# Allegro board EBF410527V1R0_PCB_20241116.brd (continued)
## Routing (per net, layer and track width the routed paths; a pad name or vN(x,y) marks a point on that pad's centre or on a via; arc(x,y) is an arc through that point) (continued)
VO_LCDC_D9: length 53.7
  TOP w0.152: J7.22 v1(40.02,51.02) ; v1(27.58,28.96) 27.58,28.95 U3.104
  BOTTOM w0.152: v1(40.02,51.02) 40.5,51.51 40.5,54.36 40.2,54.66 27.43,54.66 26.52,53.74 26.52,50.16 27.76,48.92 27.76,46 29.46,44.3 30.57,44.3 31.11,43.76 31.11,39.97 30.63,39.49 27.91,39.49 27.69,39.27 27.69,29.06 v1(27.58,28.96)
VO_LCDC_D10: length 54.3
  TOP w0.152: v1(39.02,52.02) 39.52,51.52 J7.21 ; U3.38 55.77,19.06 55.5,19.33 55.5,22.2 55.02,22.68 55.02,37.97 55.3,38.25 55.3,38.99 v1(54.73,39.56)
  GND02 w0.152: v1(39.02,52.02) 39.5,51.54 39.5,50.69 40.11,50.09 40.11,45.29 40.41,44.98 44.98,44.98 45.29,44.68 45.29,39.73 45.95,39.07 54.23,39.07 v1(54.73,39.56)
VO_LCDC_D11: length 52.7
  TOP w0.152: v1(54.73,38.56) 54.58,38.42 54.58,22.4 55.07,21.92 55.07,18.26 55.37,17.96 U3.37 ; J7.20 v1(39.02,51.02)
  GND02 w0.152: v1(54.73,38.56) 45.69,38.56 44.83,39.42 44.83,44.27 44.53,44.58 40.11,44.58 39.73,44.96 39.73,49.89 39.02,50.59 v1(39.02,51.02)
VO_LCDC_D12: length 45.2
  TOP w0.152: v1(54.73,41.56) 55.22,41.07 55.22,40.28 54.98,40.04 54.52,40.04 54.24,39.76 54.24,39.75 54.15,39.66 54.15,22.23 54.64,21.74 54.64,17.16 54.94,16.85 U3.36 ; J7.33 45.52,48.46 46.1,47.88 51.03,47.88 52.31,46.6 v1(52.52,46.6)
  BOTTOM w0.152: v1(54.73,41.56) 54.73,41.69 54.31,42.11 54.31,44.45 52.52,46.23 v1(52.52,46.6)
VO_LCDC_D13: length 46.4
  TOP w0.152: U3.35 54.46,15.76 54.15,16.06 54.15,21.54 53.77,21.92 53.77,39.88 54.45,40.56 v1(54.73,40.56) ; v1(51.52,46.6) 50.57,47.55 46,47.55 45.02,48.53 J7.32
  BOTTOM w0.152: v1(54.73,40.56) 54.24,41.04 54.24,41.74 54,41.99 54,44.3 51.7,46.6 v1(51.52,46.6)
VO_LCDC_D14: length 47.1
  TOP w0.152: v1(50.52,46.6) 50.43,46.6 49.89,47.14 45.98,47.14 44.52,48.6 J7.31 ; v1(53.73,40.56) 53.73,40.39 53.31,39.98 53.31,21.72 53.72,21.31 53.72,15.24 54.31,14.66 U3.34
  BOTTOM w0.152: v1(50.52,46.6) 50.52,46.12 50.93,45.72 51.56,45.72 53.24,44.04 53.24,41.04 v1(53.73,40.56)
VO_LCDC_D15: length 49.5
  TOP w0.152: J7.30 44.02,48.67 45.92,46.76 49.36,46.76 v1(49.52,46.6) ; U3.33 54.59,13.55 53.34,14.81 53.34,21.01 52.91,21.44 52.91,40.06 53.21,40.36 53.21,40.38 53.21,40.39 53.21,41.05 v1(53.73,41.56)
  BOTTOM w0.152: v1(53.73,41.56) 53.67,41.62 53.67,44.15 51.71,46.1 51.26,46.1 51.04,46.32 51.04,46.81 50.76,47.09 50.02,47.09 v1(49.52,46.6)
VO_LCDC_D16: length 52.2
  TOP w0.152: J7.29 v1(43.52,48.74) ; U3.31 55.27,11.36 52.48,14.15 52.48,20.45 52.12,20.8 52.12,40.96 v1(52.73,41.56)
  GND02 w0.152: v1(52.73,41.56) 48.66,41.56 47.85,42.37 47.85,47.42 47.55,47.73 43.82,47.73 43.52,48.03 v1(43.52,48.74)
VO_LCDC_D17: length 51.9
  TOP w0.152: J7.28 43.02,49.09 42.67,48.74 v1(42.52,48.74) ; v1(52.73,40.56) 52.53,40.36 52.53,21.08 52.91,20.7 52.91,14.48 54.93,12.45 U3.32
  GND02 w0.152: v1(42.52,48.74) 42.52,47.5 42.82,47.19 47.09,47.19 47.4,46.89 47.4,42.04 48.87,40.56 v1(52.73,40.56)
VO_LCDC_DEN: length 46.9
  TOP w0.152: v1(32.41,47.85) 33.02,48.47 J7.8 ; v1(37.97,38.59) 40.25,38.59 41.15,37.69 41.15,30.91 40.69,30.45 40.69,23.24 42.01,21.92 42.01,11.94 40.73,10.65 U3.15
  BOTTOM w0.152: v1(32.41,47.85) 32.51,47.85 34.7,45.67 34.7,42.11 37.97,38.84 v1(37.97,38.59)
VO_LCDC_HSYNC: length 42.7
  TOP w0.152: v1(37.97,37.59) 38.46,38.07 40.08,38.07 40.77,37.39 40.77,31.06 40.36,30.66 40.36,22.91 41.53,21.74 41.53,12.57 39.63,10.67 U3.14
  BOTTOM w0.152: R96.1 34.32,45.26 34.32,41.96 37.37,38.91 37.37,38.4 37.97,37.8 v1(37.97,37.59)
VO_LCDC_VSYNC: length 40.7
  TOP w0.152: v1(39.24,37.59) 39.93,37.59 40.41,37.11 40.41,31.24 40.01,30.84 40.01,12.12 38.52,10.64 U3.13
  BOTTOM w0.152: v1(39.24,37.59) 39.24,38.03 35.03,42.24 35.03,46.18 R97.1
WIFI_PWR_EN: length 33.6
  TOP w0.152: R52.1 68.15,33.61 68.15,23.4 v1(68.01,23.27)
  BOTTOM w0.152: v1(68.01,23.27) 67.53,23.75 66.8,23.75 66.53,23.47 66.53,21.97 66.22,21.66 50.25,21.66 49.76,22.14 U5.6
XL9535_INT: length 48.4
  TOP w0.152: U3.114 29.75,17.96 31.64,16.06 v1(31.64,12.12) ; v1(48.95,13.94) 48.95,21.74 50.06,22.86 50.06,23.67 48.77,24.97 v1(48.77,29.08)
  BOTTOM w0.152: R25.1 48.52,29.08 v1(48.77,29.08) ; v1(31.64,12.12) 31.92,12.4 42.55,12.4 44.09,13.94 v1(48.95,13.94)
N19537137: length 11.4
  TOP w0.203: U17.8 62.99,45.47 62.74,45.21 60.07,45.21 59.69,45.59 59.69,48.9 58.93,49.66 57.66,49.66 57.35,49.97 J11.1
N19537140: length 26.3
  TOP w0.203: 66.45,44.02 59.49,44.02 58.8,44.7 58.8,48.36 58.39,48.77 56.35,48.77 56.1,49.02 J11.2 ; 66.45,44.02 66.8,44.37 U17.5 ; 66.45,44.02 66.9,43.56 66.9,43.08 67.64,42.34 67.64,39.17 68.07,38.73 68.7,38.73 R86.2
N19537426: length 4.3
  TOP w0.203: U17.4 66.8,38.6 R85.2
  TOP w0.254: R86.1 R85.2
N19538834: length 6.4
  TOP w0.203: v1(65.53,39.85) U17.3 65.53,42.27 65.3,42.49 64.57,42.49 64.26,42.19 U17.2
  BOTTOM w0.254: C55.1 67.04,39.85 v1(65.53,39.85)
N21425973: length 2.3
  TOP w0.152: J1.A5 79.56,11.04 v1(79.81,10.79)
  BOTTOM w0.152: R5.1 v1(79.81,10.79)
N21425975: length 2.3
  TOP w0.152: J1.B5 v1(79.76,14.04)
  BOTTOM w0.152: R4.1 79.96,13.84 v1(79.76,14.04)
N21432968: length 9.3
  TOP w0.157: v1(83.24,12.77) 82.93,12.47 82.02,12.47 81.52,11.97 79.66,11.97 79.59,12.04 ; 79.59,12.04 79.68,12.13 79.68,12.9 79.54,13.04 J1.B6 ; 79.59,12.04 J1.A6
  BOTTOM w0.157: R2.1 82.54,12.83 D1.2 83.18,12.84 v1(83.24,12.77)
N21432971: length 10.3
  TOP w0.157: J1.A7 77.25,12.54 77.09,12.38 77.09,11.7 77.25,11.54 J1.B7 79.59,11.54 79.66,11.61 81.67,11.61 82.17,12.11 82.93,12.11 v1(83.24,11.81)
  BOTTOM w0.157: v1(83.24,11.81) 82.56,11.81 D2.2 82.54,11.81 R3.1
N23042290: length 3.8
  TOP w0.152: v1(32.41,3.17) 32.41,1.96 32.78,1.58 LED2.2
  BOTTOM w0.152: R9.2 32.51,3.28 v1(32.41,3.17)
N23042305: length 3.4
  TOP w0.152: Q1.3 36.49,3.49 35.61,2.62 LED2.1
N23503644: length 8.9
  TOP w0.152: 15.77,42.17 15.6,42.34 15.6,43.31 15.42,43.48 15.14,43.48 14.94,43.28 14.94,42.56 14.78,42.41 14.57,42.41 14.33,42.65 14.33,43.08 14.17,43.23 13.67,43.23 13.36,43.54 13.36,43.97 13.59,44.19 J2.1
  TOP w0.157: 15.77,42.17 D10.1 R16.2
N23503648: length 6.8
  TOP w0.152: D9.1 16.1,44.2 15.8,44.5 15.8,45.04 15.54,45.29
  TOP w0.157: D9.1 16.9,44.64 17.17,44.91 19.13,44.91 19.44,44.59 R17.2 ; 15.54,45.29 J2.2
N23503652: length 7.6
  TOP w0.157: J2.3 15.46,46.39 15.62,46.55 15.62,46.79 15.77,46.94 16.05,46.94 16.33,46.66 16.33,45.64 16.51,45.47 D8.1 16.9,45.88 17.17,46.15 19.18,46.15 19.44,45.89 R18.2
N23503668: length 7.9
  TOP w0.157: J2.7 15.37,50.79 15.57,50.59 15.57,48.7 15.73,48.54 16.36,48.54 D6.1 17.51,48.62 19.23,48.62 19.44,48.4 R19.2
N23503672: length 19
  TOP w0.157: R20.2 18.84,41.1 17.48,41.1 D5.1 16.31,41.1 14.3,41.1 12.29,43.1 12.29,50.75 13.44,51.89 J2.8
N23503676: length 10.5
  TOP w0.157: R21.2 19.44,49.57 19.08,49.94 17.69,49.94 D4.1 16.75,49 16.21,49 16,49.2 16,49.73 16.16,49.89 16.48,49.89 16.61,50.01 16.61,50.39 16.48,50.52 16.15,50.52 15.95,50.72 15.95,52.68 15.64,52.99 J2.9
N23656759: length 5.5
  TOP w0.254: U2.5 v1(71.31,9.04)
  BOTTOM w0.254: R10.2 C5.2 R13.1 70.7,9.65 v1(71.31,9.04)
N23695731: length 5.9
  BOTTOM w0.157: Y1.3 38.6,16.55 38.38,16.76 38.38,19.07 C15.1 38.5,19.72 U6.3
N23695751: length 4.4
  BOTTOM w0.157: U6.4 38,19.72 C16.2 38.07,19.12 38.07,18.21 37.91,18.05 Y1.1
N23695813: length 2.2
  BOTTOM w0.152: R43.2 39.5,26.3 U6.18
N23695825: length 1.8
  BOTTOM w0.152: U6.16 38.5,27.29 R41.2
N23695839: length 2
  BOTTOM w0.152: U6.17 39,26.82 R39.2
N23695875: length 2
  BOTTOM w0.152: U6.13 37,26.89 R44.1
N23697039: length 1.7
  BOTTOM w0.152: R48.1 1.82,23.84 U8.3
N23697128: length 4
  BOTTOM w0.152: R46.1 2.35,32.92 2.35,30.92 1.82,30.39 U7.3
N23704623: length 11.7
  BOTTOM w0.152: U15.4 68.49,49.49 68.71,49.28 69.97,49.28 R67.2 R68.1 71.47,48.79 72.73,48.79 73.03,49.09 73.03,50.93 73.41,51.31 75.82,51.31 76.11,51.02 U16.4
N23704651: length 4
  BOTTOM w0.152: U16.3 76.11,53.65 76.3,53.85 77.24,53.85 77.44,53.64 R69.1
N23704740: length 4.1
  BOTTOM w0.152: U15.3 68.49,53.63 68.68,53.82 69.8,53.82 69.98,53.64 R66.1
N23717309: length 26.6
  TOP w1.016: R77.1 19.05,20.45 C47.1 17.02,18.36 16.18,17.53 J8.13
  BOTTOM w1.016: J8.13 J8.14
N23717611: length 6
  TOP w0.152: C46.1 18.09,14.23 17.68,13.82 17.68,11.68 16.41,10.42 J8.4
N23717616: length 7.5
  TOP w0.152: J8.5 13.85,8.5 15.82,6.53 18.86,6.53 C45.1
N23717674: length 11.2
  BOTTOM w0.124: R73.2 20.89,8.79 20.55,9.13 18.83,9.13 18.24,9.72 18.24,11.34 18.05,11.53 15.77,11.53 14.94,12.37 14.94,13.15 J8.1
N23717677: length 11.8
  BOTTOM w0.124: J8.2 16.39,13.72 16.15,13.97 15.51,13.97 15.26,13.72 15.26,12.51 15.91,11.86 18.19,11.86 18.57,11.48 18.57,9.86 18.96,9.46 20.55,9.46 20.89,9.8 R72.2
N23717680: length 11.1
  BOTTOM w0.124: R71.2 20.89,7.77 20.55,7.43 18.46,7.43 18.18,7.71 18.18,8.84 17.74,9.28 15.38,9.28 15.04,9.63 15.04,11.4 14.75,11.69 J8.3
N23717683: length 9.4
  BOTTOM w0.124: J8.6 15.56,7.88 15.34,8.1 15.34,8.71 15.59,8.95 17.6,8.95 17.85,8.71 17.85,7.57 18.32,7.1 20.55,7.1 20.89,6.76 R70.2
N23718997: length 3.7
  TOP w0.508: U10.2 C26.1 C24.2
N23719030: length 3.8
  TOP w0.152: Q2.1 68.27,34.86 R52.2 68.33,35.81 R51.2 C27.2
N23719056: length 5.9
  TOP w0.157: U10.4 63.62,27.2 63.78,27.36 65.38,27.36 v1(65.68,27.06)
  BOTTOM w0.157: v1(65.68,27.06) 66.01,27.38 66.91,27.38 67.24,27.05 R50.2
N23719058: length 5.9
  TOP w0.157: U10.5 63.62,27.87 63.78,27.72 65.38,27.72 v1(65.68,28.02)
  BOTTOM w0.157: R49.2 67.24,28.07 66.91,27.74 65.96,27.74 v1(65.68,28.02)
N23719088: length 3.1
  TOP w0.508: CN1.1 C25.1 C24.1
N23722440: length 10.9
  TOP w0.203: R81.2 76.97,47.9 76.52,47.9 75.84,47.22 74.24,47.22 73.58,47.88 72.13,47.88 C48.1 70.86,47.88 70.03,47.88 69.47,47.32 R79.2
N23723488: length 3.5
  TOP w0.203: R80.2 68.46,46.1 C49.1 R82.2
N23729410: length 2.1
  TOP w0.152: v1(28.07,5.53) 28.06,5.52 Q3.1
  BOTTOM w0.152: R76.2 27.48,4.94 v1(28.07,5.53)
N23729602: length 2.1
  TOP w0.152: v1(31.7,5.28) 31.46,5.28 31.22,5.52 Q4.1
  BOTTOM w0.152: R78.2 31.36,4.94 v1(31.7,5.28)
N23729707: length 21.3
  TOP w0.152: R75.2 18.25,17.26 16.92,15.93 12.24,15.93 9.25,12.93 4.19,12.93 3.89,13.23 3.89,15.12 J8.9
N23729710: length 40.8
  TOP w0.152: Q4.3 30.33,4.57 30.02,4.88 30.02,5.84 29.65,6.21 26.5,6.21 26.16,6.55 20.88,6.55 20.27,5.94 20.27,4.62 19.89,4.24 14.25,4.24 10.85,7.65 2.91,7.65 2.61,7.95 J8.10
N23729715: length 31.4
  TOP w0.152: Q3.3 26.7,4.57 26.34,4.93 26.34,5.84 25.97,6.21 21.03,6.21 20.65,5.83 20.65,4.47 20.02,3.84 13.63,3.84 10.41,7.06 3.97,7.06 J8.11
N23729724: length 21.5
  TOP w0.152: R74.2 14.39,2.29 10.16,6.53 5.16,6.53 4.65,6.02 4.65,3.58 4.22,3.15 J8.12
N23759751: length 2.3
  TOP w0.152: v1(35.36,5.13) 35.36,5.22 35.05,5.52 Q1.1
  BOTTOM w0.152: R11.2 35.17,4.94 v1(35.36,5.13)
N23760169: length 2.6
  TOP w0.152: LED1.2 28.52,2.61 v1(29.08,3.17)
  BOTTOM w0.152: v1(29.08,3.17) R8.2
N23768401: length 2.6
  BOTTOM w0.152: R93.1 R59.2 68.51,44.27 U13.4
N23768412: length 2.9
  BOTTOM w0.152: R60.1 69.33,45.86 68.51,46.68 U13.3
N23768535: length 2.5
  BOTTOM w0.152: U14.4 47,45.23 R92.1 R61.2
N23768546: length 1.4
  BOTTOM w0.152: U14.3 47.27,47.73 R62.1
N23809669: length 23.8
  TOP w0.152: R53.2 19.43,34.37 19.96,34.89 19.96,35.79 R56.2 20.02,36.9 20.02,37.9 19.44,38.47 C30.1 18.91,37.95 17.63,37.95 17.42,37.74 17.42,36.47 17.27,36.32 U12.5 16.21,36.32 14.76,37.77 11.96,37.77 11.4,38.33 v1(11.4,42.76)
  BOTTOM w0.152: J14.7 v1(11.4,42.76)
N23809673: length 20.1
  TOP w0.152: R55.2 C32.1 16.85,34.19 U12.6 16.22,35.82 14.66,37.39 11.63,37.39 10.79,38.24 v1(10.79,44.03)
  BOTTOM w0.152: J14.2 v1(10.79,44.03)
N23809721: length 14.8
  TOP w0.157: v1(16.11,38.22) 16.11,37.32 16.6,36.82 U12.4 16.85,38.45 C31.1 R54.2
  BOTTOM w0.157: J14.3 12.11,41.49 11.89,41.27 11.89,38.61 12.27,38.23 16.1,38.23 v1(16.11,38.22)
N23809831: length 2.6
  BOTTOM w0.157: R58.1 31.81,32.79 31.13,32.79 30.91,33.01 J4.38
N23809847: length 2.6
  BOTTOM w0.157: R57.1 31.81,32.43 31.13,32.43 30.91,32.21 J4.36
N23819356: length 6.9
  TOP w0.152: R87.2 D11.2 80.54,30.52 ; 80.54,30.52 80.84,30.22 SW2.3 ; 80.54,30.52 80.84,30.83 SW2.4
N23820735: length 1
  TOP w0.254: R85.1 C54.2
N23825175: length 3
  BOTTOM w0.152: U5.24 47.96,26.04 48.62,26.7 49.17,26.7 R28.2
N23825177: length 2.8
  BOTTOM w0.152: R27.2 48.12,26.67 47.68,26.67 47.46,26.45 U5.23
N23825179: length 3.2
  BOTTOM w0.152: U5.18 44.76,25.99 R26.2
N23825209: length 2.4
  BOTTOM w0.152: U5.19 45.46,26.3 R23.2
N23825224: length 2.2
  BOTTOM w0.152: U5.20 45.96,26.82 R24.2
N23825226: length 2.3
  BOTTOM w0.152: U5.22 46.96,26.52 R25.2
N23825314: length 6.7
  BOTTOM w0.152: U4.6 46.31,29.94 46.66,29.59 50.5,29.59 50.8,29.29 R22.2
N23848065: length 6.9
  TOP w0.152: 80.59,37.89 80.84,38.14 SW3.4 ; 80.59,37.89 D12.2 R90.2 ; 80.59,37.89 80.84,37.63 SW3.3
N23848217: length 9.3
  TOP w0.152: SW4.3 80.84,45.03 80.61,45.25 ; 80.61,45.25 D13.2 R91.2 80.14,47 80.14,48.01 79.63,48.51 R94.1 ; 80.61,45.25 80.84,45.48 SW4.4
N23865153: length 2.8
  TOP w0.152: v1(33.41,47.85) 33.52,47.97 J7.9
  BOTTOM w0.152: v1(33.41,47.85) 33.91,47.35 R97.2
N23865156: length 7.2
  TOP w0.152: v1(31.41,47.85) 31.89,47.37 33.66,47.37 34.02,47.74 J7.10
  BOTTOM w0.152: R96.2 32.21,47.37 32.21,47.37 31.72,47.85 v1(31.41,47.85)
N23865159: length 8.4
  TOP w0.157: J7.11 34.52,47.45 33.93,46.86 31.98,46.86 v1(31.95,46.89)
  BOTTOM w0.157: R95.2 33.78,44.98 31.95,46.81 v1(31.95,46.89)

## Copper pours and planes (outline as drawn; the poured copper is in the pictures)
GND on TOP: 3,0.51 1.24,1.24 0.51,3 0.51,53 1.24,54.76 3,55.49 16,55.49 16.35,55.35 16.49,55 16.49,52.5 18.5,50.49 20.51,52.5 20.51,55 20.65,55.35 21,55.49 82,55.49 83.76,54.76 84.49,53 84.49,3 83.76,1.24 82,0.51 ; 216 cut-outs
GND on BOTTOM: 3,0.51 1.24,1.24 0.51,3 0.51,53 1.24,54.76 3,55.49 16,55.49 16.35,55.35 16.49,55 16.49,52.5 18.5,50.49 20.51,52.5 20.51,55 20.65,55.35 21,55.49 82,55.49 83.76,54.76 84.49,53 84.49,3 83.76,1.24 82,0.51 ; 144 cut-outs
GND on GND02: 3,0.51 1.24,1.24 0.51,3 0.51,53 1.24,54.76 3,55.49 16,55.49 16.35,55.35 16.49,55 16.49,52.5 18.5,50.49 20.51,52.5 20.51,55 20.65,55.35 21,55.49 82,55.49 83.76,54.76 84.49,53 84.49,3 83.76,1.24 82,0.51 ; 38 cut-outs
GND on PWR03: 3,0.51 1.24,1.24 0.51,3 0.51,53 1.24,54.76 3,55.49 16,55.49 16.35,55.35 16.49,55 16.49,52.5 18.5,50.49 20.51,52.5 20.51,55 20.65,55.35 21,55.49 82,55.49 83.76,54.76 84.49,53 84.49,3 83.76,1.24 82,0.51
VCC5V0_SYS on TOP: 68.55,41.58 69.19,41.58 69.39,41.78 69.39,42.14 69.57,42.32 70.51,42.32 70.92,41.91 70.92,40.44 70.64,40.16 69.65,40.16 69.01,40.79 68.55,40.79
VCC5V0_SYS on TOP: 79.35,10.19 76.4,10.19 76.28,10.31 76.28,12.97 77,13.69 77,14.19 77.22,14.4 79.35,14.4 79.35,15.01 75.54,15.01 74.75,14.22 74.75,9.37 74.47,9.09 72.19,9.09 71.96,8.86 71.96,7.47 71.78,7.29 70.51,7.29 70.36,7.44 70.36,8.41 69.98,8.79 69.04,8.79 68.96,8.71 68.96,6.02 69.27,5.71 75.9,5.71 76.2,6.02 76.2,7.21 77.11,8.13 77.11,9.47 77.24,9.6 79.35,9.6
VCC5V0_SYS on TOP: 51.44,46.15 51.44,42.67 51.64,42.47 52.83,42.47 53.14,42.77 53.14,46.15
VCC5V0_SYS on BOTTOM: 3.4,27.99 3.63,28.22 5.61,28.22 5.79,28.04 5.79,27.79 5.59,27.58 4.83,27.58 4.7,27.46 4.7,25.88 4.55,25.73 3.58,25.73 3.4,25.91
VCC5V0_SYS on BOTTOM: 3.4,31.11 3.61,30.91 4.55,30.91 4.75,31.11 4.75,32.59 4.93,32.77 5.71,32.77 5.82,32.87 5.82,33.55 5.66,33.71 3.91,33.71 3.76,33.55 3.76,32.59 3.4,32.23
VCC5V0_SYS on BOTTOM: 66.93,45.82 66.29,45.82 64.67,44.2 64.67,40.84 64.95,40.56 69.22,40.56 69.65,40.13 70.61,40.13 70.89,40.41 70.89,42.06 70.61,42.34 69.42,42.34 68.88,41.81 65.94,41.81 65.79,41.96 65.79,43.71 66.7,44.63 66.93,44.63
VCC5V0_SYS on BOTTOM: 66.29,49.68 67.74,49.68 67.84,49.78 67.84,51.05 67.94,51.16 68.68,51.16 68.81,51.28 68.81,51.69 68.71,51.79 67.21,51.79 66.29,50.88
VCC5V0_SYS on BOTTOM: 43.81,45.85 43.81,44.32 44.7,43.43 47.85,43.43 48.21,43.79 50.8,43.79 51.05,43.54 51.05,42.65 51.38,42.32 52.83,42.32 53.01,42.49 53.01,43.81 51.44,45.39 47.98,45.39 47.59,45 46.98,45 46.48,44.5 45.34,44.5 45.11,44.73 45.11,45.67 44.93,45.85
VCC5V0_SYS on GND02: outline of 115 points within 3.17,1.14 83.79,52.7
VCC_3V3 on TOP: 66.17,37.21 70.26,37.21 70.27,37.2 70.6,37.2 71.35,36.45 71.35,33.76 71.2,33.6 70.08,33.6 69.82,33.86 69.82,36.25 69.72,36.35 66.17,36.35
VCC_3V3 on TOP: 65.15,14.17 65.41,14.43 66.52,14.43 66.73,14.63 66.73,16.48 66.47,16.74 64.06,16.74 63.78,16.46 63.78,10.82 63.42,10.46 63.42,8.13 64.9,8.13 65.15,8.38
VCC_3V3 on BOTTOM: 73.91,50.88 73.91,48.26 74.19,47.98 78.74,47.98 79.35,47.37 79.35,35.92 78.82,35.38 70.15,35.38 70.15,35.36 69.82,35.03 69.82,33.55 70.21,33.17 81.08,33.17 81.61,33.71 81.61,48.13 80.24,49.5 74.68,49.5 74.52,49.66 74.52,50.88
VCC_3V3 on BOTTOM: 66.57,16.59 66.93,16.23 67.94,16.23 68.38,15.8 68.38,12.4 67.77,12.4 67.77,13.21 67.36,13.61 67.36,14.22 67.11,14.48 65.28,14.48 65.15,14.61 65.15,16.38 65.35,16.59
VCC_3V3 on BOTTOM: 33.05,37.54 31.37,37.54 31.17,37.34 31.17,35.92 31.29,35.79 31.67,35.79 31.85,35.97 31.85,36.42 32.16,36.73 33.05,36.73
VCC_3V3 on BOTTOM: 22.56,34.49 20.55,34.49 20.55,33.91 20.4,33.76 19.96,33.76 19.86,33.66 19.86,33.25 20.02,33.1 22.56,33.1
VCC_3V3 on GND02: 66.45,18.31 67.49,19.35 69.42,19.35 71.42,21.36 71.42,35.15 70.43,36.14 65.71,36.14 65.51,35.94 65.51,31.6 64.85,30.94 63.3,30.94 62.99,30.63 62.99,25.76 60.35,23.11 60.35,23.09 60.17,22.91 60.17,19.99 59.99,19.81 56.24,19.81 55.8,20.24 55.8,22.4 55.19,23.01 55.19,34.85 54.76,35.28 46.69,35.28 46.3,34.9 46.3,30.38 45.92,30 43.56,30 43,30.56 43,37.85 42.42,38.43 42.42,40.72 41.76,41.38 36.35,41.38 33.55,38.58 31.37,38.58 30.96,38.18 30.96,36.07 31.22,35.81 34.77,35.81 35.33,35.26 36.68,35.26 37.31,35.89 37.31,36.93 37.69,37.31 39.8,37.31 40.28,36.83 40.28,31.37 39.75,30.84 39.75,12.17 38.25,10.67 38.25,9.6 38.48,9.37 49.86,9.37 50.16,9.68 50.16,10.41 50.37,10.62 56.67,10.62 56.68,10.63 57.04,10.63 57.38,10.97 60.07,10.97 63.45,14.35 66.14,14.35 66.45,14.66
VDD_CAM0_5V on BOTTOM: 66.93,48.34 60.38,48.34 60.12,48.59 60.12,50.11 58.83,50.11 58.83,48.36 59.94,47.24 63.02,47.24 63.58,46.69 65.38,46.69 65.84,47.14 66.93,47.14
VDD_CAM1_5V on BOTTOM: 40.64,50.09 40.64,48.87 40.92,48.59 40.92,46.76 40.97,46.71 42.7,46.71 43.08,47.09 44.4,47.09 44.4,48.34 42.75,48.34 41.94,49.15 41.94,50.09
VDD_LCD_3V3 on TOP: 48.18,49.2 48.18,52.58 48.36,52.76 49.17,52.76 49.33,52.91 49.33,53.59 49.23,53.7 47.55,53.7 47.37,53.52 47.37,49.2
VDD_LCD_3V3 on BOTTOM: 70.69,51.71 70.69,53.75 69.93,54.51 60.45,54.51 58.67,52.73 48.01,52.73 47.83,52.91 47.83,53.64 48.06,53.87 57.73,53.87 59.08,55.22 70.97,55.22 72.82,53.37 74.52,53.37 74.52,52.17 73.15,52.17 72.69,51.71
VDD_LCD_5V on TOP: 48.36,49.2 49.23,49.2 49.33,49.3 49.33,52.2 49.17,52.35 48.51,52.35 48.36,52.2
VDD_LCD_5V on BOTTOM: 63.55,51.69 66.42,51.69 66.9,52.17 66.9,53.37 64.34,53.37 63.47,54.23 60.5,54.23 58.85,52.58 48.9,52.58 48.72,52.4 48.72,51.08 48.84,50.95 49.35,50.95 49.91,51.51 59.13,51.51 60.93,53.31 62.69,53.31 63.17,52.83 63.17,52.07
MICIN0_N on TOP (solid shape): 74.3,49.84 74.25,49.76 74.16,49.75 73.4,50.2 73.76,51.1 74.2,51.8
MICIN1_P on TOP (solid shape): 66.23,51.1 66.6,50.2 65.84,49.73 65.74,49.73 65.7,49.82 65.8,51.8
USB_VBUS0 on BOTTOM: 5.13,30.28 7.04,30.28 7.04,28.88 6.76,28.6 3.43,28.6 3.43,29.79 4.65,29.79
USB_VBUS1 on BOTTOM: 3.4,25.5 4.57,25.5 5.03,25.96 6.91,25.96 6.91,24.56 6.63,24.28 3.4,24.28
N23656755 on TOP: 69.72,11.13 67.34,11.13 67.03,10.82 67.03,8.1 68.45,8.1 68.45,9.73 68.63,9.91 69.72,9.91
N23717674 on BOTTOM (solid shape): 14.92,13.23 14.9,13.18 14.85,13.17 12.85,13.43 13.84,14.24 14.85,15.03

Small or netless copper shapes (teardrops, artwork), in the pictures only: 25 on TOP, 17 on BOTTOM

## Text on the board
Ref Des/Silkscreen Bottom: CAM RX1 | CAM RX0 | 20241116 | EBF410527V1R0 | SIM
Ref Des/Silkscreen Top: TF_CARD | PWR | SYS | 19 | SPK | SET | MIC2 | 9 | GND | MIC1 | RX | TX | A | RESET | ADC | REC | USB | ETH | WIFI | RGB | Display
COMPVAL_TYPE_TOP: SW1 | SW2 | 40 | 140 | 111 | 110 | EBF410458V0R1 | 20240229 | RST | 30 | JLCJLCJLCJLCJLCJLC | MIPI_DSI | KEY | 25 | 26 | PWR | SYS | TX | RX | GND | 71 | 41 | 70 | A | SPK | 1 | 2 | J3 | J4 | J5 | J6 | R95 | D14 | R99 | D15 | U7 | J11 | J10 | U11 | R81 | R80 | C48 | R1 | D4 | R2 | D2 | D3 | D1 | C50 | P1 | R85 | C51 | R86 | J9 | J1 | J2 | J8 | USB2 | USB1 | ETH | IR | TF CARD | PHONE | MIC | LED2 | C32 | C31 | LED1 | C49 | C52
COMPVAL_TYPE_BOTTOM: 39 | 40 | 1 | MIPI CSI | 24 | PWR | FAN | SYS | GPIO | RTC | GND | RXD | TXD | IR | 2 | USB OTG | HDMI | EAR+MIC | USB2.0X2 | USB3.0+USB2.0 | ETH0 | REC | MR | TF Card
User.6: FIGURE | SIZE | 10.0 | 35.43 | 39.37 | 40.16 | 78.74 | 125.98 | 25.59 | 43.31 | 62.99 | 102.36 | 140.0 | 47.2x23.6 | 66.9x23.6 | 80.0x40.0 | DRILL CHART: TOP to BOTTOM | ALL UNITS ARE IN MILS | PLATED | NON-PLATED | QTY | 726 | 8 | 3 | 30 | 4 | 2 | 1
